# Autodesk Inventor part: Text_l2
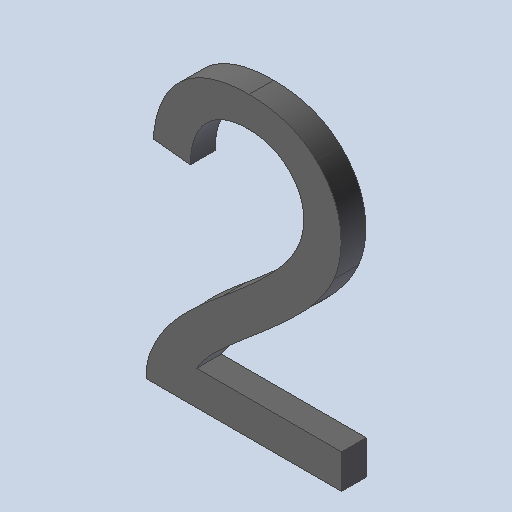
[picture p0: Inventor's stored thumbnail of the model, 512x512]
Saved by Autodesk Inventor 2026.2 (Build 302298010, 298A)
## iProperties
Created: 2026-10
Part Number: Text_l2
Material: Générique
Document SubType Name: Modeling
Designer: mel
Density: 1 g/cm^3
Appearance: Par défaut
Author: mel
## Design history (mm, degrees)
feature "Base1"
node "Solide1"
